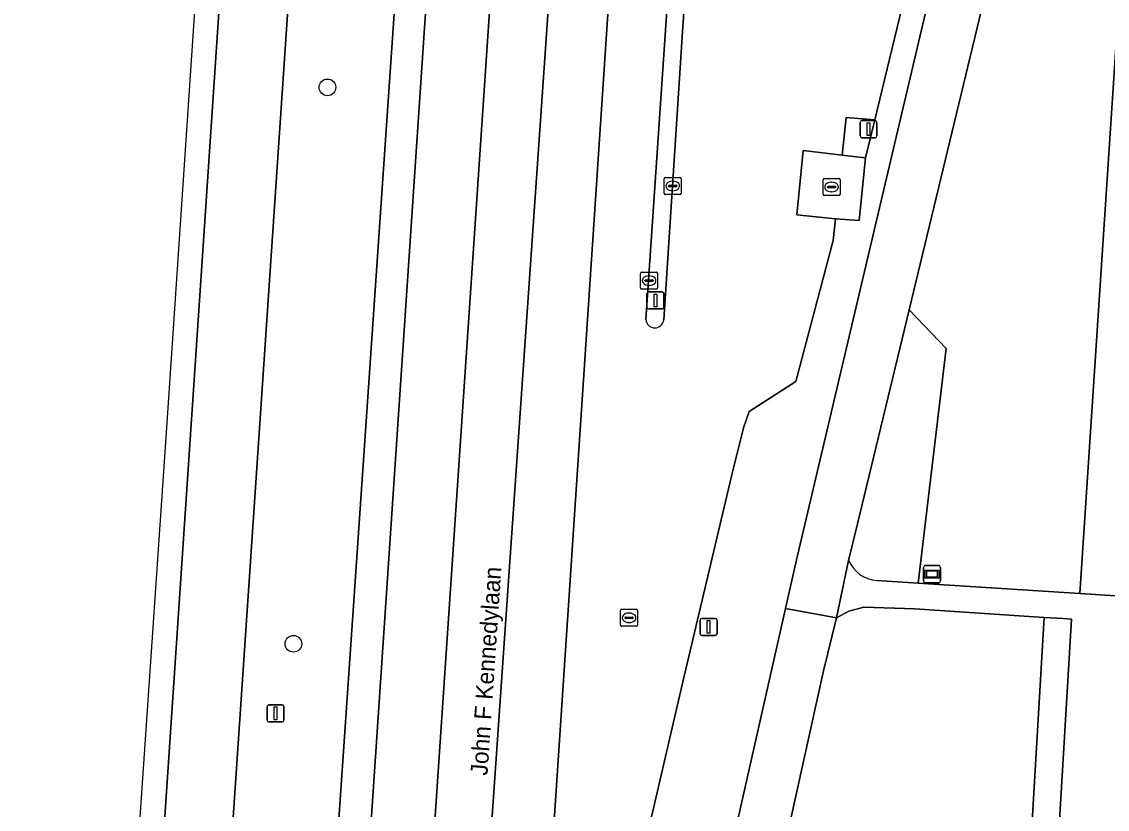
# Model space of a CAD drawing. Extents: x 161848 to 162726, y 385382 to 386521.
# Drawn here: x 161874 to 161937.7, y 385865.9 to 385912.2 of the extents above; entities that cross this region are included whole.
import ezdxf

# ---------------------------------------------------------------- set-up
doc = ezdxf.new("R2010")
doc.units = 0
for name, color, linetype in [('IMGEO_Berm_groen', 7, 'Continuous'), ('IMGEO_Boom', 7, 'Continuous'), ('IMGEO_Fietspad_gesloten', 7, 'Continuous'), ('IMGEO_Groenvoorziening', 7, 'Continuous'), ('IMGEO_Haag', 7, 'Continuous'), ('IMGEO_Kolk', 7, 'Continuous'), ('IMGEO_Lichtmast', 7, 'Continuous'), ('IMGEO_Openbare_ruimte_label', 7, 'Continuous'), ('IMGEO_Rijbaan_lokaal_open', 7, 'Continuous'), ('IMGEO_Rijbaan_regionaal_gesloten', 7, 'Continuous'), ('IMGEO_Straatnaambord', 7, 'Continuous'), ('IMGEO_Verkeerseiland_open', 7, 'Continuous'), ('IMGEO_Voetpad_open', 7, 'Continuous')]:
    doc.layers.add(name, color=color, linetype=linetype)

msp = doc.modelspace()

# ---------------------------------------------------------------- linework, layer by layer
at = {"layer": 'IMGEO_Berm_groen'}
for points in [[(161891.348, 385999.175), (161889.369, 385969.842), (161881.653, 385855.03), (161875.71, 385766.607), (161876.708, 385766.537), (161886.669, 385765.84), (161887.667, 385765.77), (161889.229, 385787.874), (161890.255, 385802.397), (161892.576, 385836.929), (161893.738, 385854.209), (161900.311, 385951.981), (161902.378, 385982.726), (161903.388, 385997.75)], [(161934.076, 385932.542), (161932.676, 385923.695), (161930.423, 385913.464), (161926.031, 385895.262), (161928.213, 385892.993), (161926.577, 385879.216), (161936.046, 385878.605), (161941.769, 385965.23)], [(161928.213, 385892.993), (161926.031, 385895.262), (161923.002, 385882.707), (161922.49, 385880.558)], [(161924.139, 385879.373), (161926.577, 385879.216), (161928.213, 385892.993)]]:
    msp.add_lwpolyline(points, dxfattribs=at)
for points in [[(161898.617, 385953.379), (161892.662, 385958.293), (161885.657, 385854.758), (161884.117, 385831.999), (161890.551, 385835.749)], [(161898.617, 385953.379), (161890.551, 385835.749), (161884.117, 385831.999), (161885.657, 385854.758), (161892.662, 385958.293)], [(161927.156, 385913.357), (161927.986, 385917.325), (161928.496, 385919.768), (161928.954, 385921.705), (161928.324, 385921.865), (161927.628, 385920.047), (161927.083, 385918.11), (161926.479, 385916.549), (161924.032, 385906.413), (161923.477, 385904.186), (161923.109, 385900.51), (161921.722, 385900.609), (161921.589, 385899.331), (161919.383, 385891.049), (161916.653, 385889.292), (161916.321, 385888.332), (161915.609, 385885.499), (161912.752, 385873.422), (161908.706, 385855.98), (161913.235, 385853.143), (161918.782, 385877.729), (161919.429, 385880.598)]]:
    msp.add_lwpolyline(points, close=True, dxfattribs=at)
msp.add_arc((161924.295, 385881.33), 1.963, 203.15389, 265.44276, dxfattribs=at)
at = {"layer": 'IMGEO_Boom'}
for centre in [(161891.909, 385908.319), (161889.909, 385875.66)]:
    msp.add_circle(centre, 0.489, dxfattribs=at)
at = {"layer": 'IMGEO_Fietspad_gesloten'}
for points in [[(161929.35, 385923.544), (161928.958, 385921.721), (161928.954, 385921.705), (161928.496, 385919.768), (161927.986, 385917.325), (161927.156, 385913.357), (161919.429, 385880.598), (161918.782, 385877.729), (161921.773, 385877.183), (161922.49, 385880.558), (161923.002, 385882.707), (161926.031, 385895.262), (161930.423, 385913.464)], [(161916.36, 385853.003), (161921.012, 385874.074), (161921.773, 385877.183), (161918.782, 385877.729), (161913.235, 385853.143)]]:
    msp.add_lwpolyline(points, dxfattribs=at)
at = {"layer": 'IMGEO_Groenvoorziening'}
msp.add_lwpolyline([(161956.172, 385964.297), (161951.778, 385964.617), (161951.81, 385965.293), (161952.514, 385975.741), (161942.908, 385976.416), (161942.155, 385965.203), (161941.769, 385965.23), (161936.046, 385878.605), (161945.908, 385877.969), (161947.252, 385877.882), (161947.664, 385883.893), (161946.303, 385883.992), (161946.959, 385893.98), (161951.459, 385893.64)], dxfattribs=at)
for points in [[(161932.486, 385852.287), (161933.97, 385877.214), (161926.374, 385877.711), (161923.382, 385877.802), (161922.501, 385877.573), (161921.773, 385877.183), (161921.012, 385874.074), (161916.36, 385853.003), (161924.731, 385852.628)], [(161935, 385867.588), (161935.567, 385877.109), (161935.068, 385877.142), (161933.97, 385877.214), (161932.486, 385852.287), (161933.585, 385852.239), (161934.084, 385852.209)]]:
    msp.add_lwpolyline(points, close=True, dxfattribs=at)
at = {"layer": 'IMGEO_Haag'}
msp.add_lwpolyline([(161935, 385867.588), (161935.567, 385877.109), (161935.068, 385877.142), (161933.97, 385877.214), (161932.486, 385852.287), (161933.585, 385852.239), (161934.084, 385852.209)], close=True, dxfattribs=at)
at = {"layer": 'IMGEO_Kolk'}
for p, q in [((161911.741, 385903.028), (161912.593, 385903.028)), ((161911.666, 385902.102), (161911.666, 385902.954)), ((161911.925, 385902.522), (161911.925, 385902.534)), ((161912.363, 385902.485), (161911.965, 385902.485)), ((161911.968, 385902.571), (161912.366, 385902.571)), ((161912.154, 385902.808), (161912.179, 385902.808)), ((161912.409, 385902.534), (161912.409, 385902.522)), ((161912.667, 385902.954), (161912.667, 385902.102)), ((161920.986, 385902.043), (161920.986, 385902.895)), ((161921.061, 385902.969), (161921.913, 385902.969)), ((161921.245, 385902.463), (161921.245, 385902.475)), ((161921.683, 385902.426), (161921.285, 385902.426)), ((161921.288, 385902.512), (161921.686, 385902.512)), ((161921.474, 385902.749), (161921.499, 385902.749)), ((161921.729, 385902.475), (161921.729, 385902.463)), ((161921.987, 385902.895), (161921.987, 385902.043)), ((161912.593, 385902.028), (161911.741, 385902.028)), ((161912.177, 385902.248), (161912.152, 385902.248)), ((161921.913, 385901.969), (161921.061, 385901.969)), ((161921.497, 385902.189), (161921.472, 385902.189)), ((161910.28, 385896.55), (161910.28, 385897.402)), ((161910.355, 385897.476), (161911.207, 385897.476)), ((161911.281, 385897.402), (161911.281, 385896.55)), ((161910.539, 385896.97), (161910.539, 385896.982)), ((161910.977, 385896.933), (161910.579, 385896.933)), ((161910.582, 385897.019), (161910.98, 385897.019)), ((161910.791, 385896.696), (161910.766, 385896.696)), ((161910.768, 385897.256), (161910.793, 385897.256)), ((161911.023, 385896.982), (161911.023, 385896.97)), ((161911.207, 385896.476), (161910.355, 385896.476)), ((161909.106, 385876.761), (161909.106, 385877.613)), ((161909.181, 385877.687), (161910.033, 385877.687)), ((161910.107, 385877.613), (161910.107, 385876.761)), ((161909.365, 385877.181), (161909.365, 385877.193)), ((161909.803, 385877.144), (161909.405, 385877.144)), ((161909.408, 385877.23), (161909.806, 385877.23)), ((161909.617, 385876.907), (161909.592, 385876.907)), ((161909.594, 385877.467), (161909.619, 385877.467)), ((161909.849, 385877.193), (161909.849, 385877.181)), ((161910.033, 385876.687), (161909.181, 385876.687))]:
    msp.add_line(p, q, dxfattribs=at)
for points in [[(161911.741, 385903.028), (161912.593, 385903.028)], [(161911.666, 385902.102), (161911.666, 385902.954)], [(161912.667, 385902.954), (161912.667, 385902.102)], [(161920.986, 385902.043), (161920.986, 385902.895)], [(161921.061, 385902.969), (161921.913, 385902.969)], [(161921.987, 385902.895), (161921.987, 385902.043)], [(161912.593, 385902.028), (161911.741, 385902.028)], [(161921.913, 385901.969), (161921.061, 385901.969)], [(161910.28, 385896.55), (161910.28, 385897.402)], [(161910.355, 385897.476), (161911.207, 385897.476)], [(161911.281, 385897.402), (161911.281, 385896.55)], [(161911.207, 385896.476), (161910.355, 385896.476)], [(161909.106, 385876.761), (161909.106, 385877.613)], [(161909.181, 385877.687), (161910.033, 385877.687)], [(161910.107, 385877.613), (161910.107, 385876.761)], [(161910.033, 385876.687), (161909.181, 385876.687)]]:
    msp.add_lwpolyline(points, dxfattribs=at)
for centre, radius, start, end in [((161911.743, 385902.952), 0.0765, 91.55205, 178.44795), ((161911.743, 385902.952), 0.0765, 91.55205, 178.44795), ((161912.591, 385902.952), 0.0765, 1.55205, 88.44795), ((161912.591, 385902.952), 0.0765, 1.55205, 88.44795), ((161911.965, 385902.531), 0.0403, 85.87752, 175.75265), ((161911.962, 385902.521), 0.0366, 178.93798, 274.71019), ((161912.366, 385902.528), 0.043, 264.86636, 352.45326), ((161912.37, 385902.533), 0.0386, 1.73085, 96.63898), ((161921.063, 385902.893), 0.0765, 91.55205, 178.44795), ((161921.063, 385902.893), 0.0765, 91.55205, 178.44795), ((161921.285, 385902.472), 0.0403, 85.87752, 175.75265), ((161921.282, 385902.462), 0.0366, 178.93798, 274.71019), ((161921.686, 385902.469), 0.043, 264.86636, 352.45326), ((161921.69, 385902.474), 0.0386, 1.73085, 96.63898), ((161921.911, 385902.893), 0.0765, 1.55205, 88.44795), ((161921.911, 385902.893), 0.0765, 1.55205, 88.44795), ((161911.743, 385902.104), 0.0765, 181.55205, 268.44795), ((161911.743, 385902.104), 0.0765, 181.55205, 268.44795), ((161912.591, 385902.104), 0.0765, 271.55205, 358.44795), ((161912.591, 385902.104), 0.0765, 271.55205, 358.44795), ((161921.063, 385902.045), 0.0765, 181.55205, 268.44795), ((161921.063, 385902.045), 0.0765, 181.55205, 268.44795), ((161921.911, 385902.045), 0.0765, 271.55205, 358.44795), ((161921.911, 385902.045), 0.0765, 271.55205, 358.44795), ((161910.357, 385897.4), 0.0765, 91.55205, 178.44795), ((161910.357, 385897.4), 0.0765, 91.55205, 178.44795), ((161911.205, 385897.4), 0.0765, 1.55205, 88.44795), ((161911.205, 385897.4), 0.0765, 1.55205, 88.44795), ((161910.579, 385896.979), 0.0403, 85.87752, 175.75265), ((161910.576, 385896.969), 0.0366, 178.93798, 274.71019), ((161910.98, 385896.976), 0.043, 264.86636, 352.45326), ((161910.984, 385896.981), 0.0386, 1.73085, 96.63898), ((161910.357, 385896.552), 0.0765, 181.55205, 268.44795), ((161910.357, 385896.552), 0.0765, 181.55205, 268.44795), ((161911.205, 385896.552), 0.0765, 271.55205, 358.44795), ((161911.205, 385896.552), 0.0765, 271.55205, 358.44795), ((161909.183, 385877.611), 0.0765, 91.55205, 178.44795), ((161909.183, 385877.611), 0.0765, 91.55205, 178.44795), ((161910.031, 385877.611), 0.0765, 1.55205, 88.44795), ((161910.031, 385877.611), 0.0765, 1.55205, 88.44795), ((161909.405, 385877.19), 0.0403, 85.87752, 175.75265), ((161909.402, 385877.18), 0.0366, 178.93798, 274.71019), ((161909.806, 385877.187), 0.043, 264.86636, 352.45326), ((161909.81, 385877.192), 0.0386, 1.73085, 96.63898), ((161909.183, 385876.763), 0.0765, 181.55205, 268.44795), ((161909.183, 385876.763), 0.0765, 181.55205, 268.44795), ((161910.031, 385876.763), 0.0765, 271.55205, 358.44795), ((161910.031, 385876.763), 0.0765, 271.55205, 358.44795)]:
    msp.add_arc(centre, radius, start, end, dxfattribs=at)
for centre, major_axis, ratio, start_param, end_param in [((161912.153, 385902.528), (-0.387, 0.002), 0.722429, 4.712389, 7.853982), ((161912.178, 385902.528), (-0.39, 0.002), 0.717154, 1.570796, 4.712389), ((161921.473, 385902.469), (-0.387, 0.002), 0.722429, 4.712389, 7.853982), ((161921.498, 385902.469), (-0.39, 0.002), 0.717154, 1.570796, 4.712389), ((161910.767, 385896.976), (-0.387, 0.002), 0.722429, 4.712389, 7.853982), ((161910.792, 385896.976), (-0.39, 0.002), 0.717154, 1.570796, 4.712389), ((161909.593, 385877.187), (-0.387, 0.002), 0.722429, 4.712389, 7.853982), ((161909.618, 385877.187), (-0.39, 0.002), 0.717154, 1.570796, 4.712389)]:
    msp.add_ellipse(centre, major_axis=major_axis, ratio=ratio, start_param=start_param, end_param=end_param, dxfattribs=at)
at = {"layer": 'IMGEO_Lichtmast'}
for p, q in [((161923.157, 385905.465), (161923.157, 385906.265)), ((161923.157, 385906.265), (161923.157, 385905.465)), ((161923.257, 385906.365), (161924.047, 385906.365)), ((161924.047, 385906.365), (161923.257, 385906.365)), ((161924.147, 385906.265), (161924.147, 385905.465)), ((161924.147, 385905.465), (161924.147, 385906.265)), ((161924.047, 385905.365), (161923.257, 385905.365)), ((161923.257, 385905.365), (161924.047, 385905.365)), ((161910.656, 385895.415), (161910.656, 385896.215)), ((161910.656, 385896.215), (161910.656, 385895.415)), ((161910.756, 385896.315), (161911.546, 385896.315)), ((161911.546, 385896.315), (161910.756, 385896.315)), ((161911.646, 385896.215), (161911.646, 385895.415)), ((161911.646, 385895.415), (161911.646, 385896.215)), ((161911.546, 385895.315), (161910.756, 385895.315)), ((161910.756, 385895.315), (161911.546, 385895.315)), ((161913.777, 385876.254), (161913.777, 385877.054)), ((161913.777, 385877.054), (161913.777, 385876.254)), ((161913.877, 385877.154), (161914.667, 385877.154)), ((161914.667, 385877.154), (161913.877, 385877.154)), ((161914.767, 385877.054), (161914.767, 385876.254)), ((161914.767, 385876.254), (161914.767, 385877.054)), ((161914.667, 385876.154), (161913.877, 385876.154)), ((161913.877, 385876.154), (161914.667, 385876.154)), ((161888.364, 385871.179), (161888.364, 385871.979)), ((161888.364, 385871.979), (161888.364, 385871.179)), ((161888.464, 385872.079), (161889.254, 385872.079)), ((161889.254, 385872.079), (161888.464, 385872.079)), ((161889.354, 385871.979), (161889.354, 385871.179)), ((161889.354, 385871.179), (161889.354, 385871.979)), ((161889.254, 385871.079), (161888.464, 385871.079)), ((161888.464, 385871.079), (161889.254, 385871.079))]:
    msp.add_line(p, q, dxfattribs=at)
for points in [[(161923.577, 385906.24), (161923.727, 385906.24), (161923.727, 385905.49), (161923.577, 385905.49), (161923.577, 385906.24)], [(161911.076, 385896.19), (161911.226, 385896.19), (161911.226, 385895.44), (161911.076, 385895.44), (161911.076, 385896.19)], [(161914.197, 385877.029), (161914.347, 385877.029), (161914.347, 385876.279), (161914.197, 385876.279), (161914.197, 385877.029)], [(161888.784, 385871.954), (161888.934, 385871.954), (161888.934, 385871.204), (161888.784, 385871.204), (161888.784, 385871.954)]]:
    msp.add_lwpolyline(points, dxfattribs=at)
for centre, start, end in [((161923.257, 385906.265), 90, 180), ((161923.257, 385906.265), 90, 180), ((161924.047, 385906.265), 0, 90), ((161924.047, 385906.265), 360, 90), ((161923.257, 385905.465), 180, 270), ((161923.257, 385905.465), 180, 270), ((161924.047, 385905.465), 270, 0), ((161924.047, 385905.465), 270, 0), ((161910.756, 385896.215), 90, 180), ((161910.756, 385896.215), 90, 180), ((161911.546, 385896.215), 0, 90), ((161911.546, 385896.215), 360, 90), ((161910.756, 385895.415), 180, 270), ((161910.756, 385895.415), 180, 270), ((161911.546, 385895.415), 270, 0), ((161911.546, 385895.415), 270, 0), ((161913.877, 385877.054), 90, 180), ((161913.877, 385877.054), 90, 180), ((161914.667, 385877.054), 0, 90), ((161914.667, 385877.054), 360, 90), ((161913.877, 385876.254), 180, 270), ((161913.877, 385876.254), 180, 270), ((161914.667, 385876.254), 270, 0), ((161914.667, 385876.254), 270, 0), ((161888.464, 385871.979), 90, 180), ((161888.464, 385871.979), 90, 180), ((161889.254, 385871.979), 0, 90), ((161889.254, 385871.979), 360, 90), ((161888.464, 385871.179), 180, 270), ((161888.464, 385871.179), 180, 270), ((161889.254, 385871.179), 270, 0), ((161889.254, 385871.179), 270, 0)]:
    msp.add_arc(centre, 0.1, start, end, dxfattribs=at)
at = {"layer": 'IMGEO_Rijbaan_lokaal_open'}
for points in [[(161922.582, 385960.787), (161922.424, 385961.911), (161922.303, 385962.773), (161921.988, 385968.004), (161918.498, 385996.361), (161913.944, 385996.717), (161904.434, 385853.538), (161903.301, 385836.47), (161906.731, 385836.162), (161906.817, 385837.841), (161906.92, 385839.853), (161907.462, 385846.994)], [(161910.593, 385894.692), (161915.187, 385962.357), (161915.256, 385963.349)], [(161922.337, 385906.552), (161924.032, 385906.413), (161926.479, 385916.549), (161927.083, 385918.11), (161927.628, 385920.047), (161928.324, 385921.865), (161928.359, 385921.957), (161928.585, 385922.689), (161928.819, 385923.64)], [(161913.351, 385914.864), (161912.946, 385914.481), (161912.747, 385911.57), (161911.643, 385894.679)], [(161908.706, 385855.98), (161912.752, 385873.422), (161915.609, 385885.499), (161916.321, 385888.332), (161916.653, 385889.292), (161919.383, 385891.049), (161921.589, 385899.331), (161921.722, 385900.609), (161919.455, 385900.841), (161919.828, 385904.612), (161922.102, 385904.34), (161922.337, 385906.552)]]:
    msp.add_lwpolyline(points, dxfattribs=at)
msp.add_lwpolyline([(161924.032, 385906.413), (161922.337, 385906.552), (161922.102, 385904.34), (161923.477, 385904.186)], close=True, dxfattribs=at)
msp.add_arc((161911.119, 385894.73), 0.527, 184.12164, 354.45968, dxfattribs=at)
at = {"layer": 'IMGEO_Rijbaan_regionaal_gesloten'}
for points in [[(161873.969, 385764.259), (161875.54, 385764.148), (161875.71, 385766.607), (161881.653, 385855.03), (161889.369, 385969.842), (161891.348, 385999.175), (161889.915, 385999.289), (161882.5, 385888.923)], [(161897.442, 385853.958), (161907.136, 385997.383), (161903.388, 385997.75), (161902.378, 385982.726), (161900.311, 385951.981), (161893.738, 385854.209), (161892.576, 385836.929), (161890.255, 385802.397), (161889.229, 385787.874), (161887.667, 385765.77), (161887.496, 385763.329), (161891.235, 385763.071)], [(161910.537, 385997.05), (161907.136, 385997.383), (161897.442, 385853.958), (161891.235, 385763.071), (161894.471, 385762.848), (161896.507, 385791.78), (161900.748, 385853.733), (161908.023, 385958.495)], [(161913.944, 385996.717), (161910.537, 385997.05), (161908.023, 385958.495), (161900.748, 385853.733), (161896.507, 385791.78), (161894.471, 385762.848), (161898.148, 385762.594), (161898.829, 385774.203), (161902.398, 385822.88), (161903.301, 385836.47), (161904.434, 385853.538)]]:
    msp.add_lwpolyline(points, close=True, dxfattribs=at)
at = {"layer": 'IMGEO_Straatnaambord'}
for p, q in [((161926.887, 385879.349), (161926.887, 385880.149)), ((161926.887, 385880.149), (161926.887, 385879.349)), ((161926.987, 385880.249), (161927.777, 385880.249)), ((161927.777, 385880.249), (161926.987, 385880.249)), ((161927.877, 385880.149), (161927.877, 385879.349)), ((161927.877, 385879.349), (161927.877, 385880.149)), ((161927.777, 385879.249), (161926.987, 385879.249)), ((161926.987, 385879.249), (161927.777, 385879.249))]:
    msp.add_line(p, q, dxfattribs=at)
for points in [[(161926.988, 385879.981), (161927.776, 385879.981), (161927.776, 385879.517), (161926.988, 385879.517), (161926.988, 385879.981)], [(161927.053, 385879.916), (161927.053, 385879.582), (161927.711, 385879.582), (161927.711, 385879.916), (161927.053, 385879.916)]]:
    msp.add_lwpolyline(points, dxfattribs=at)
for centre, start, end in [((161926.987, 385880.149), 90, 180), ((161926.987, 385880.149), 90, 180), ((161927.777, 385880.149), 0, 90), ((161927.777, 385880.149), 360, 90), ((161926.987, 385879.349), 180, 270), ((161926.987, 385879.349), 180, 270), ((161927.777, 385879.349), 270, 0), ((161927.777, 385879.349), 270, 0)]:
    msp.add_arc(centre, 0.1, start, end, dxfattribs=at)
at = {"layer": 'IMGEO_Verkeerseiland_open'}
for points in [[(161915.256, 385963.349), (161915.187, 385962.357), (161910.593, 385894.692)], [(161911.643, 385894.679), (161912.747, 385911.57), (161912.946, 385914.481), (161913.351, 385914.864)]]:
    msp.add_lwpolyline(points, dxfattribs=at)
msp.add_arc((161911.119, 385894.73), 0.527, 184.12164, 354.45968, dxfattribs=at)
at = {"layer": 'IMGEO_Voetpad_open'}
msp.add_lwpolyline([(161923.477, 385904.186), (161922.102, 385904.34), (161919.828, 385904.612), (161919.455, 385900.841), (161921.722, 385900.609), (161923.109, 385900.51)], close=True, dxfattribs=at)
for points in [[(161922.49, 385880.558), (161921.773, 385877.183), (161922.501, 385877.573), (161923.382, 385877.802), (161926.374, 385877.711), (161933.97, 385877.214), (161935.068, 385877.142), (161935.567, 385877.109), (161935, 385867.588), (161934.084, 385852.209), (161933.818, 385847.74), (161943.973, 385847.108), (161944.063, 385848.44), (161948.372, 385848.216)], [(161960.809, 385875.198), (161951.247, 385875.773), (161951.359, 385877.618), (161947.252, 385877.882), (161945.908, 385877.969), (161936.046, 385878.605), (161926.577, 385879.216), (161924.139, 385879.373)]]:
    msp.add_lwpolyline(points, dxfattribs=at)
msp.add_arc((161924.295, 385881.33), 1.963, 203.15389, 265.44276, dxfattribs=at)

# ---------------------------------------------------------------- texts
at = {"layer": 'IMGEO_Openbare_ruimte_label'}
msp.add_text('John F Kennedylaan', height=1, rotation=86.15925, dxfattribs=at).set_placement((161901.294, 385867.91))

doc.saveas('drawing.dxf')
